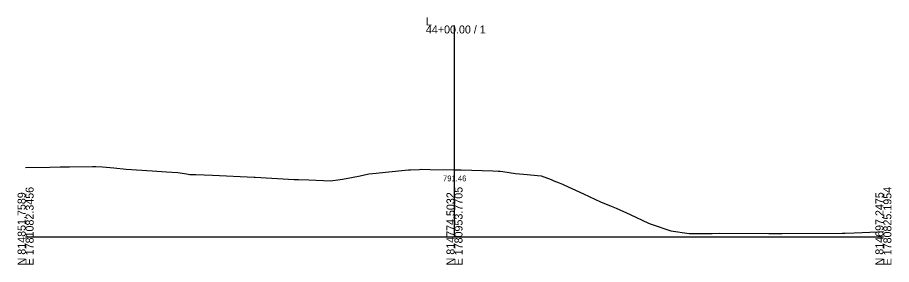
# Model space of a CAD drawing. Extents: x -26 to 7903, y -10 to 9573.
# Drawn here: x 997.2 to 1302.8, y 4990.3 to 5076.8 of the extents above; entities that cross this region are included whole.
import ezdxf

# ---------------------------------------------------------------- set-up
doc = ezdxf.new("R2010")
doc.units = 0
for name, color, linetype in [('Exist Cross Section Cell', 7, 'Continuous'), ('Exist XS Center Line Elevation Label', 7, 'Continuous'), ('Exist XS Ground Line', 7, 'Continuous')]:
    doc.layers.add(name, color=color, linetype=linetype)

msp = doc.modelspace()

# ---------------------------------------------------------------- linework, layer by layer
at = {"layer": 'Exist Cross Section Cell'}
for p, q in [((1150, 5000), (1150, 5073.98)), ((1000, 5000), (1150, 5000)), ((1150, 5000), (1300, 5000))]:
    msp.add_line(p, q, dxfattribs=at)
at = {"layer": 'Exist XS Ground Line'}
for p, q in [((1000, 5024.23), (1008.5, 5024.42)), ((1008.5, 5024.42), (1012.07, 5024.49)), ((1012.07, 5024.49), (1015.35, 5024.54)), ((1015.35, 5024.54), (1023.4, 5024.66)), ((1023.4, 5024.66), (1024.59, 5024.63)), ((1024.59, 5024.63), (1026.94, 5024.55)), ((1026.94, 5024.55), (1030.84, 5024.14)), ((1030.84, 5024.14), (1035.14, 5023.65)), ((1035.14, 5023.65), (1044.32, 5023.07)), ((1044.32, 5023.07), (1049.31, 5022.76)), ((1049.31, 5022.76), (1053.27, 5022.47)), ((1053.27, 5022.47), (1054.05, 5022.4)), ((1054.05, 5022.4), (1056.27, 5022.06)), ((1122.58, 5022.24), (1125.85, 5022.58)), ((1125.85, 5022.58), (1133.93, 5023.44)), ((1133.93, 5023.44), (1134.63, 5023.51)), ((1134.63, 5023.51), (1137.78, 5023.62)), ((1137.78, 5023.62), (1138.49, 5023.65)), ((1138.49, 5023.65), (1141.44, 5023.6)), ((1141.44, 5023.6), (1150, 5023.46)), ((1150, 5023.46), (1151.59, 5023.43)), ((1151.59, 5023.43), (1152.34, 5023.41)), ((1152.34, 5023.41), (1163.38, 5023.14)), ((1163.38, 5023.14), (1165.29, 5023.03)), ((1165.29, 5023.03), (1165.95, 5022.99)), ((1165.95, 5022.99), (1166.9, 5022.86)), ((1166.9, 5022.86), (1171.34, 5022.17)), ((1056.27, 5022.06), (1057.41, 5021.84)), ((1057.41, 5021.84), (1059.57, 5021.8)), ((1059.57, 5021.8), (1065.39, 5021.58)), ((1065.39, 5021.58), (1079.99, 5020.89)), ((1079.99, 5020.89), (1080.29, 5020.88)), ((1080.29, 5020.88), (1093.95, 5020.11)), ((1093.95, 5020.11), (1095.1, 5020.04)), ((1095.1, 5020.04), (1095.4, 5020.05)), ((1095.4, 5020.05), (1099.11, 5019.99)), ((1099.11, 5019.99), (1104.17, 5019.73)), ((1104.17, 5019.73), (1106.63, 5019.59)), ((1106.63, 5019.59), (1110.06, 5020.07)), ((1110.06, 5020.07), (1110.88, 5020.19)), ((1110.88, 5020.19), (1113.98, 5020.75)), ((1113.98, 5020.75), (1117.03, 5021.36)), ((1117.03, 5021.36), (1120.05, 5022.01)), ((1120.05, 5022.01), (1122.58, 5022.24)), ((1171.34, 5022.17), (1174.15, 5021.88)), ((1174.15, 5021.88), (1180.34, 5021.38)), ((1180.34, 5021.38), (1183.77, 5020.03)), ((1183.77, 5020.03), (1184.77, 5019.61)), ((1184.77, 5019.61), (1186.56, 5018.94)), ((1186.56, 5018.94), (1187.75, 5018.48)), ((1187.75, 5018.48), (1188.28, 5018.25)), ((1188.28, 5018.25), (1195.08, 5015.05)), ((1195.08, 5015.05), (1201.06, 5012.24)), ((1201.06, 5012.24), (1204.8, 5010.71)), ((1204.8, 5010.71), (1206.59, 5009.99)), ((1206.59, 5009.99), (1211.42, 5007.77)), ((1211.42, 5007.77), (1217.88, 5004.79)), ((1217.88, 5004.79), (1218.8, 5004.44)), ((1218.8, 5004.44), (1225.6, 5002.14)), ((1225.6, 5002.14), (1232.04, 5001.14)), ((1232.04, 5001.14), (1240.07, 5001.21)), ((1240.07, 5001.21), (1242.75, 5001.27)), ((1242.75, 5001.27), (1259.94, 5001.21)), ((1259.94, 5001.21), (1264.55, 5001.19)), ((1264.55, 5001.19), (1285.57, 5001.25)), ((1285.57, 5001.25), (1286.65, 5001.34)), ((1286.65, 5001.34), (1289.72, 5001.43)), ((1289.72, 5001.43), (1298.09, 5001.8)), ((1298.09, 5001.8), (1300, 5001.88))]:
    msp.add_line(p, q, dxfattribs=at)

# ---------------------------------------------------------------- texts
at = {"layer": 'Exist Cross Section Cell'}
for s, p in [('L', (1140, 5073.98)), ('44+00.00 / 1', (1140, 5071.18))]:
    msp.add_text(s, height=2.8, dxfattribs=at).set_placement(p)
for s, p in [('E 1781082.3456', (1002.8, 4990)), ('E 1780953.7705', (1152.8, 4990)), ('E 1780825.1954', (1302.8, 4990)), ('N 814851.7589', (1000, 4990)), ('N 814774.5032', (1150, 4990)), ('N 814697.2475', (1300, 4990))]:
    msp.add_text(s, height=2.8, rotation=90, dxfattribs=at).set_placement(p)
at = {"layer": 'Exist XS Center Line Elevation Label'}
msp.add_text('791.46', height=2, dxfattribs=at).set_placement((1145.97, 5019.46))

doc.saveas('drawing.dxf')
